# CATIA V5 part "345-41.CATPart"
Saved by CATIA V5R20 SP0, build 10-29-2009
Part number: 345-41
Definition: NONE
Nomenclature: 345-41
Source: Unknown
Description: 345-41
Bounding box of the stored display mesh (mm): x 0 to 80, y -41.5 to 41.5, z -41.5 to 41.5
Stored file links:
  C:\Users\Utente\Desktop\IO LAVORO\3D X SITO CF\X SITO\345-346\345-41.CATPart
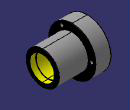
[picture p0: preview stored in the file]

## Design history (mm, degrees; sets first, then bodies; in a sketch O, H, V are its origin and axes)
Body1 "345-41" (main body)
  Solid1: solid without history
